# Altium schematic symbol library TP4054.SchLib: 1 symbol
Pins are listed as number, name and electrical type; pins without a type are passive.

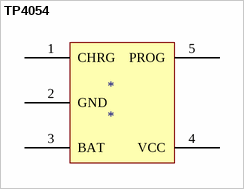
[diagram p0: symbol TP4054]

## TP4054
designator *
pins: 1 CHRG, 2 GND, 3 BAT, 4 VCC, 5 PROG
